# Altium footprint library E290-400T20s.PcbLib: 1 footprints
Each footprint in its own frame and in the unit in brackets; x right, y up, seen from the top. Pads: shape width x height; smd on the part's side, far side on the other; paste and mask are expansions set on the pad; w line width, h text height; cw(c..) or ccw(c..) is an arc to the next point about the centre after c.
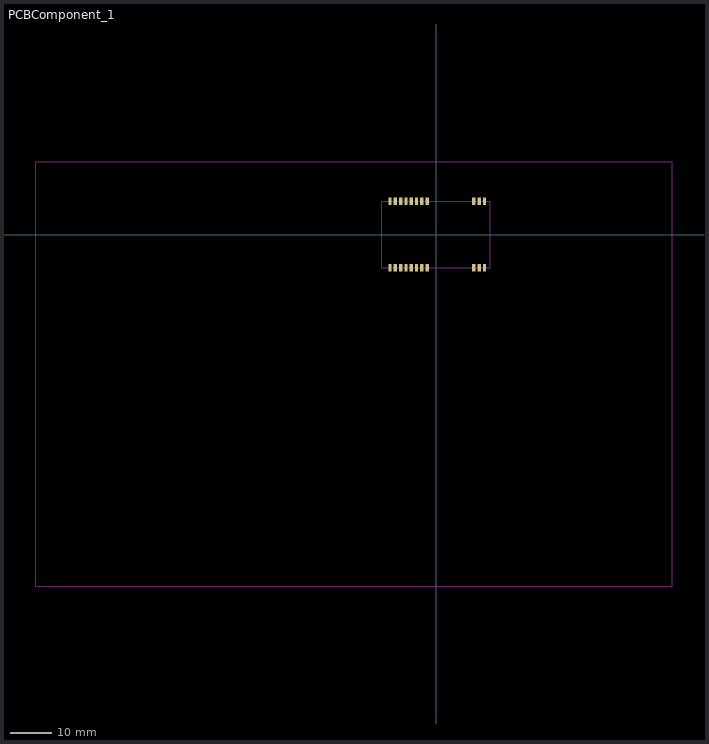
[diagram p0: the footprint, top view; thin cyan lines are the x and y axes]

## PCBComponent_1 [mm]
pads (22):
  rect 0.8x1.8 smd paste+0 mask+0: 1(11.569,8.035) 2(10.299,8.035) 3(9.029,8.035) 4(-2.141,8.035) 5(-3.411,8.035) 6(-4.681,8.035) 7(-5.951,8.035) 8(-7.221,8.035) 9(-8.491,8.035) 10(-9.761,8.035) 11(-11.031,8.035) 12(-11.031,-7.965) 13(-9.761,-7.965) 14(-8.491,-7.965) 15(-7.221,-7.965) 16(-5.951,-7.965) 17(-4.681,-7.965) 18(-3.411,-7.965) 19(-2.141,-7.965) 20(9.029,-7.965) 21(10.299,-7.965) 23(11.569,-7.965)
Keep-Out Layer:
  lines w0.254: -95.867,-84.167 -95.867,17.433 56.533,17.433 56.533,-84.167 -95.867,-84.167 ; -13.041,-7.965 -13.041,8.035 12.959,8.035 12.959,-7.965 -13.041,-7.965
